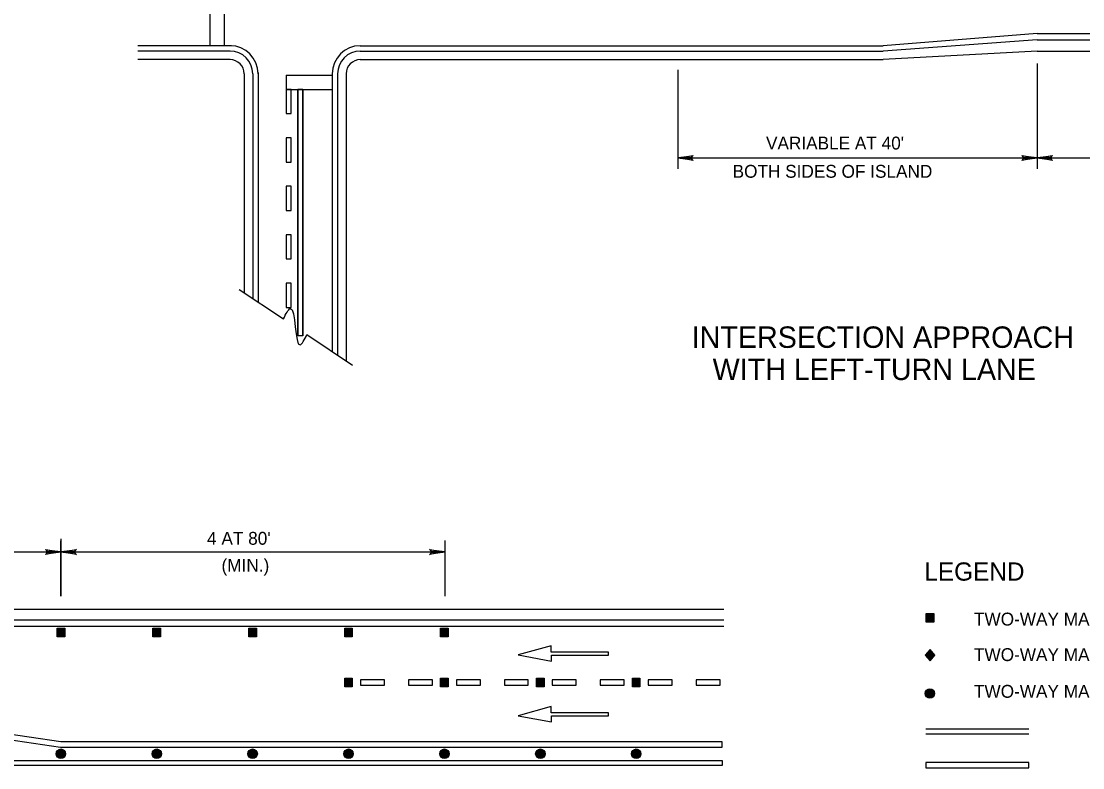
# Model space of a CAD drawing. Extents: x 639362 to 641108, y 298458 to 299646.
# Drawn here: x 639788.7 to 640036.4, y 298754.6 to 298928.7 of the extents above; entities that cross this region are included whole.
import ezdxf

# ---------------------------------------------------------------- set-up
doc = ezdxf.new("R2010")
doc.units = 0
doc.layers.add('2', color=7, linetype='Continuous')
doc.layers.add('3', color=7, linetype='Continuous')

# ---------------------------------------------------------------- blocks, each defined once
blk = doc.blocks.new('RARROW')
at = {"layer": '3'}
blk.add_lwpolyline([(-2.2695, 0.285), (-2.184875, 0.12075), (0, 0), (-2.2695, 0.285), (-2.38575, 0.384625), (0, 0), (-2.183125, -0.108), (-2.262875, -0.2705), (0, 0), (-2.38575, -0.379125), (-2.262875, -0.2705)], dxfattribs=at)

msp = doc.modelspace()

# ---------------------------------------------------------------- linework, layer by layer
at = {"layer": '2'}
for p, q in [((639832.85, 298922.95), (639832.85, 298950.59)), ((639836.15, 298922.95), (639836.15, 298950.59)), ((640025.73, 298925.85), (639989.83, 298922.95)), ((640025.73, 298925.85), (640169.33, 298925.85)), ((639837.77, 298922.95), (639815.93, 298922.95)), ((639867.83, 298922.95), (639989.83, 298922.95)), ((640025.73, 298924.35), (639989.83, 298921.72)), ((640025.73, 298924.35), (640169.33, 298924.35)), ((639837.47, 298921.72), (639815.93, 298921.72)), ((639837.47, 298919.72), (639815.93, 298919.72)), ((639867.83, 298921.72), (639989.83, 298921.72)), ((639867.83, 298919.72), (639989.83, 298919.72)), ((640025.73, 298921.72), (639989.83, 298919.72)), ((640025.73, 298921.72), (640169.33, 298921.72)), ((639941.89, 298917.32), (639941.89, 298894.23)), ((640025.73, 298918.79), (640025.73, 298894.23)), ((639840.75, 298916.44), (639840.75, 298865.35)), ((639842.75, 298916.44), (639842.75, 298864.01)), ((639843.98, 298916.69), (639843.98, 298863.19)), ((639850.53, 298916.09), (639850.53, 298912.79)), ((639850.53, 298916.09), (639861.32, 298916.09)), ((639861.32, 298916.53), (639861.32, 298851.64)), ((639862.55, 298916.44), (639862.55, 298850.81)), ((639864.55, 298916.44), (639864.55, 298849.48)), ((639850.53, 298912.79), (639861.32, 298912.79)), ((639854.47, 298912.79), (639853.27, 298912.79)), ((639853.27, 298912.79), (639853.27, 298855.27)), ((639853.27, 298855.27), (639853.27, 298912.79)), ((639853.27, 298912.79), (639854.47, 298912.79)), ((639854.47, 298855.27), (639854.47, 298912.79)), ((639854.47, 298912.79), (639854.47, 298855.27)), ((639941.89, 298896.78), (640025.73, 298896.78)), ((640025.73, 298896.78), (640169.33, 298896.78)), ((639839.62, 298866.1), (639849.91, 298859.24)), ((639854.47, 298855.27), (639853.27, 298855.27)), ((639855.4, 298855.58), (639866.03, 298848.49)), ((639797.99, 298807.92), (639797.99, 298794.58)), ((639798, 298794.58), (639798, 298807.5)), ((639887.61, 298794.58), (639887.61, 298807.59)), ((639585.52, 298804.88), (639797.99, 298804.88)), ((639798.01, 298804.88), (639887.61, 298804.88)), ((639431.25, 298791.58), (639952.64, 298791.58)), ((639789.19, 298791.58), (639951.12, 298791.58)), ((639431.25, 298789.08), (639952.64, 298789.08)), ((639789.84, 298789.08), (639951.12, 298789.08)), ((639999.84, 298790.57), (640001.61, 298790.57)), ((639999.84, 298788.53), (639999.84, 298790.57)), ((640001.61, 298788.53), (639999.84, 298788.53)), ((640000.01, 298790.4), (640001.43, 298790.4)), ((640000.01, 298788.71), (640000.01, 298790.4)), ((640001.43, 298788.71), (640000.01, 298788.71)), ((640000.19, 298790.22), (640001.26, 298790.22)), ((640000.19, 298788.89), (640000.19, 298790.22)), ((640001.26, 298788.89), (640000.19, 298788.89)), ((640000.37, 298789.07), (640000.37, 298790.04)), ((640000.37, 298790.04), (640001.08, 298790.04)), ((640001.08, 298789.07), (640000.37, 298789.07)), ((640000.55, 298789.87), (640000.9, 298789.87)), ((640000.55, 298789.24), (640000.55, 298789.87)), ((640000.9, 298789.24), (640000.55, 298789.24)), ((640000.72, 298789.69), (640000.72, 298789.42)), ((640000.9, 298789.87), (640000.9, 298789.24)), ((640001.08, 298790.04), (640001.08, 298789.07)), ((640001.26, 298790.22), (640001.26, 298788.89)), ((640001.43, 298790.4), (640001.43, 298788.71)), ((640001.61, 298790.57), (640001.61, 298788.53)), ((639431.25, 298787.58), (639952.64, 298787.58)), ((639790.24, 298787.58), (639951.12, 298787.58)), ((639797.11, 298785.06), (639797.11, 298787.1)), ((639797.11, 298787.1), (639798.88, 298787.1)), ((639797.28, 298785.23), (639797.28, 298786.92)), ((639797.28, 298786.92), (639798.7, 298786.92)), ((639797.46, 298785.41), (639797.46, 298786.74)), ((639797.46, 298786.74), (639798.53, 298786.74)), ((639797.64, 298785.59), (639797.64, 298786.56)), ((639797.64, 298786.56), (639798.35, 298786.56)), ((639797.82, 298785.76), (639797.82, 298786.39)), ((639797.82, 298786.39), (639798.17, 298786.39)), ((639798.17, 298785.76), (639797.82, 298785.76)), ((639798, 298785.94), (639798, 298786.21)), ((639798.17, 298786.39), (639798.17, 298785.76)), ((639798.35, 298786.56), (639798.35, 298785.59)), ((639798.53, 298786.74), (639798.53, 298785.41)), ((639798.7, 298786.92), (639798.7, 298785.23)), ((639798.88, 298787.1), (639798.88, 298785.06)), ((639819.47, 298785.06), (639819.47, 298787.1)), ((639819.47, 298787.1), (639821.25, 298787.1)), ((639819.65, 298785.23), (639819.65, 298786.92)), ((639819.65, 298786.92), (639821.07, 298786.92)), ((639819.83, 298785.41), (639819.83, 298786.74)), ((639819.83, 298786.74), (639820.89, 298786.74)), ((639820.01, 298785.59), (639820.01, 298786.56)), ((639820.01, 298786.56), (639820.72, 298786.56)), ((639820.18, 298785.76), (639820.18, 298786.39)), ((639820.18, 298786.39), (639820.54, 298786.39)), ((639820.54, 298785.76), (639820.18, 298785.76)), ((639820.36, 298785.94), (639820.36, 298786.21)), ((639820.54, 298786.39), (639820.54, 298785.76)), ((639820.72, 298786.56), (639820.72, 298785.59)), ((639820.89, 298786.74), (639820.89, 298785.41)), ((639821.07, 298786.92), (639821.07, 298785.23)), ((639821.25, 298787.1), (639821.25, 298785.06)), ((639841.84, 298785.06), (639841.84, 298787.1)), ((639841.84, 298787.1), (639843.62, 298787.1)), ((639842.02, 298785.23), (639842.02, 298786.92)), ((639842.02, 298786.92), (639843.44, 298786.92)), ((639842.2, 298785.41), (639842.2, 298786.74)), ((639842.2, 298786.74), (639843.26, 298786.74)), ((639842.37, 298785.59), (639842.37, 298786.56)), ((639842.37, 298786.56), (639843.08, 298786.56)), ((639842.55, 298785.76), (639842.55, 298786.39)), ((639842.55, 298786.39), (639842.91, 298786.39)), ((639842.91, 298785.76), (639842.55, 298785.76)), ((639842.73, 298785.94), (639842.73, 298786.21)), ((639842.91, 298786.39), (639842.91, 298785.76)), ((639843.08, 298786.56), (639843.08, 298785.59)), ((639843.26, 298786.74), (639843.26, 298785.41)), ((639843.44, 298786.92), (639843.44, 298785.23)), ((639843.62, 298787.1), (639843.62, 298785.06)), ((639864.21, 298785.06), (639864.21, 298787.1)), ((639864.21, 298787.1), (639865.98, 298787.1)), ((639864.39, 298785.23), (639864.39, 298786.92)), ((639864.39, 298786.92), (639865.81, 298786.92)), ((639864.56, 298785.41), (639864.56, 298786.74)), ((639864.56, 298786.74), (639865.63, 298786.74)), ((639864.74, 298785.59), (639864.74, 298786.56)), ((639864.74, 298786.56), (639865.45, 298786.56)), ((639864.92, 298785.76), (639864.92, 298786.39)), ((639864.92, 298786.39), (639865.27, 298786.39)), ((639865.27, 298785.76), (639864.92, 298785.76)), ((639865.1, 298785.94), (639865.1, 298786.21)), ((639865.27, 298786.39), (639865.27, 298785.76)), ((639865.45, 298786.56), (639865.45, 298785.59)), ((639865.63, 298786.74), (639865.63, 298785.41)), ((639865.81, 298786.92), (639865.81, 298785.23)), ((639865.98, 298787.1), (639865.98, 298785.06)), ((639886.58, 298785.06), (639886.58, 298787.1)), ((639886.58, 298787.1), (639888.35, 298787.1)), ((639886.75, 298785.23), (639886.75, 298786.92)), ((639886.75, 298786.92), (639888.17, 298786.92)), ((639886.93, 298785.41), (639886.93, 298786.74)), ((639886.93, 298786.74), (639888, 298786.74)), ((639887.11, 298785.59), (639887.11, 298786.56)), ((639887.11, 298786.56), (639887.82, 298786.56)), ((639887.29, 298785.76), (639887.29, 298786.39)), ((639887.29, 298786.39), (639887.64, 298786.39)), ((639887.64, 298785.76), (639887.29, 298785.76)), ((639887.47, 298785.94), (639887.47, 298786.21)), ((639887.64, 298786.39), (639887.64, 298785.76)), ((639887.82, 298786.56), (639887.82, 298785.59)), ((639888, 298786.74), (639888, 298785.41)), ((639888.17, 298786.92), (639888.17, 298785.23)), ((639888.35, 298787.1), (639888.35, 298785.06)), ((639798.88, 298785.06), (639797.11, 298785.06)), ((639798.7, 298785.23), (639797.28, 298785.23)), ((639798.53, 298785.41), (639797.46, 298785.41)), ((639798.35, 298785.59), (639797.64, 298785.59)), ((639821.25, 298785.06), (639819.47, 298785.06)), ((639821.07, 298785.23), (639819.65, 298785.23)), ((639820.89, 298785.41), (639819.83, 298785.41)), ((639820.72, 298785.59), (639820.01, 298785.59)), ((639843.62, 298785.06), (639841.84, 298785.06)), ((639843.44, 298785.23), (639842.02, 298785.23)), ((639843.26, 298785.41), (639842.2, 298785.41)), ((639843.08, 298785.59), (639842.37, 298785.59)), ((639865.98, 298785.06), (639864.21, 298785.06)), ((639865.81, 298785.23), (639864.39, 298785.23)), ((639865.63, 298785.41), (639864.56, 298785.41)), ((639865.45, 298785.59), (639864.74, 298785.59)), ((639888.35, 298785.06), (639886.58, 298785.06)), ((639888.17, 298785.23), (639886.75, 298785.23)), ((639888, 298785.41), (639886.93, 298785.41)), ((639887.82, 298785.59), (639887.11, 298785.59)), ((639912.39, 298782.98), (639904.67, 298780.86)), ((639904.67, 298780.86), (639912.47, 298779.39)), ((639912.39, 298781.54), (639912.39, 298782.98)), ((639925.72, 298781.54), (639912.39, 298781.54)), ((639912.47, 298779.39), (639912.47, 298780.83)), ((639912.47, 298780.83), (639925.72, 298780.83)), ((639925.72, 298780.83), (639925.72, 298781.54)), ((640000.75, 298782.1), (639999.62, 298780.8)), ((639999.62, 298780.8), (640000.75, 298779.51)), ((639999.62, 298780.8), (640001.88, 298780.8)), ((639999.73, 298780.92), (640000.85, 298779.63)), ((640000.85, 298781.98), (639999.74, 298780.7)), ((640000.96, 298781.86), (639999.83, 298780.56)), ((639999.83, 298781.04), (640000.96, 298779.75)), ((640001.06, 298781.74), (639999.93, 298780.44)), ((639999.93, 298781.16), (640001.06, 298779.87)), ((640001.17, 298781.62), (640000.04, 298780.32)), ((640000.04, 298781.28), (640001.17, 298779.99)), ((640001.27, 298781.5), (640000.14, 298780.2)), ((640000.14, 298781.4), (640001.27, 298780.11)), ((640000.25, 298781.52), (640001.38, 298780.23)), ((640001.38, 298781.38), (640000.25, 298780.08)), ((640000.35, 298781.64), (640001.48, 298780.35)), ((640001.48, 298781.26), (640000.35, 298779.96)), ((640000.46, 298781.76), (640001.58, 298780.47)), ((640001.58, 298781.14), (640000.46, 298779.84)), ((640000.56, 298781.88), (640001.69, 298780.59)), ((640001.69, 298781.02), (640000.56, 298779.72)), ((640000.67, 298782), (640001.79, 298780.71)), ((640001.79, 298780.9), (640000.67, 298779.6)), ((640001.88, 298780.8), (640000.75, 298782.1)), ((640000.75, 298782.1), (640000.75, 298779.51)), ((640000.75, 298779.51), (640001.88, 298780.8)), ((639864.21, 298773.41), (639864.21, 298775.45)), ((639864.21, 298775.45), (639865.98, 298775.45)), ((639865.98, 298773.41), (639864.21, 298773.41)), ((639864.39, 298773.59), (639864.39, 298775.27)), ((639864.39, 298775.27), (639865.81, 298775.27)), ((639865.81, 298773.59), (639864.39, 298773.59)), ((639864.56, 298773.77), (639864.56, 298775.09)), ((639864.56, 298775.09), (639865.63, 298775.09)), ((639865.63, 298773.77), (639864.56, 298773.77)), ((639864.74, 298773.94), (639864.74, 298774.92)), ((639864.74, 298774.92), (639865.45, 298774.92)), ((639865.45, 298773.94), (639864.74, 298773.94)), ((639864.92, 298774.12), (639864.92, 298774.74)), ((639864.92, 298774.74), (639865.27, 298774.74)), ((639865.27, 298774.12), (639864.92, 298774.12)), ((639865.1, 298774.29), (639865.1, 298774.56)), ((639865.27, 298774.74), (639865.27, 298774.12)), ((639865.45, 298774.92), (639865.45, 298773.94)), ((639865.63, 298775.09), (639865.63, 298773.77)), ((639865.81, 298775.27), (639865.81, 298773.59)), ((639865.98, 298775.45), (639865.98, 298773.41)), ((639873.49, 298775.03), (639867.89, 298775.03)), ((639867.89, 298775.03), (639867.89, 298773.83)), ((639867.89, 298773.83), (639873.49, 298773.83)), ((639873.49, 298773.83), (639873.49, 298775.03)), ((639884.67, 298775.03), (639879.08, 298775.03)), ((639879.08, 298775.03), (639879.08, 298773.83)), ((639879.08, 298773.83), (639884.67, 298773.83)), ((639884.67, 298773.83), (639884.67, 298775.03)), ((639886.58, 298773.41), (639886.58, 298775.45)), ((639886.58, 298775.45), (639888.35, 298775.45)), ((639888.35, 298773.41), (639886.58, 298773.41)), ((639886.75, 298773.59), (639886.75, 298775.27)), ((639886.75, 298775.27), (639888.17, 298775.27)), ((639888.17, 298773.59), (639886.75, 298773.59)), ((639886.93, 298773.77), (639886.93, 298775.09)), ((639886.93, 298775.09), (639888, 298775.09)), ((639888, 298773.77), (639886.93, 298773.77)), ((639887.11, 298773.94), (639887.11, 298774.92)), ((639887.11, 298774.92), (639887.82, 298774.92)), ((639887.82, 298773.94), (639887.11, 298773.94)), ((639887.29, 298774.12), (639887.29, 298774.74)), ((639887.29, 298774.74), (639887.64, 298774.74)), ((639887.64, 298774.12), (639887.29, 298774.12)), ((639887.47, 298774.29), (639887.47, 298774.56)), ((639887.64, 298774.74), (639887.64, 298774.12)), ((639887.82, 298774.92), (639887.82, 298773.94)), ((639888, 298775.09), (639888, 298773.77)), ((639888.17, 298775.27), (639888.17, 298773.59)), ((639888.35, 298775.45), (639888.35, 298773.41)), ((639895.85, 298775.03), (639890.26, 298775.03)), ((639890.26, 298775.03), (639890.26, 298773.83)), ((639890.26, 298773.83), (639895.85, 298773.83)), ((639895.85, 298773.83), (639895.85, 298775.03)), ((639907.04, 298775.03), (639901.45, 298775.03)), ((639901.45, 298775.03), (639901.45, 298773.83)), ((639901.45, 298773.83), (639907.04, 298773.83)), ((639907.04, 298773.83), (639907.04, 298775.03)), ((639908.94, 298773.41), (639908.94, 298775.45)), ((639908.94, 298775.45), (639910.72, 298775.45)), ((639910.72, 298773.41), (639908.94, 298773.41)), ((639909.12, 298773.59), (639909.12, 298775.27)), ((639909.12, 298775.27), (639910.54, 298775.27)), ((639910.54, 298773.59), (639909.12, 298773.59)), ((639909.3, 298773.77), (639909.3, 298775.09)), ((639909.3, 298775.09), (639910.36, 298775.09)), ((639910.36, 298773.77), (639909.3, 298773.77)), ((639909.48, 298773.94), (639909.48, 298774.92)), ((639909.48, 298774.92), (639910.19, 298774.92)), ((639910.19, 298773.94), (639909.48, 298773.94)), ((639909.65, 298774.12), (639909.65, 298774.74)), ((639909.65, 298774.74), (639910.01, 298774.74)), ((639910.01, 298774.12), (639909.65, 298774.12)), ((639909.83, 298774.29), (639909.83, 298774.56)), ((639910.01, 298774.74), (639910.01, 298774.12)), ((639910.19, 298774.92), (639910.19, 298773.94)), ((639910.36, 298775.09), (639910.36, 298773.77)), ((639910.54, 298775.27), (639910.54, 298773.59)), ((639910.72, 298775.45), (639910.72, 298773.41)), ((639918.22, 298775.03), (639912.63, 298775.03)), ((639912.63, 298775.03), (639912.63, 298773.83)), ((639912.63, 298773.83), (639918.22, 298773.83)), ((639918.22, 298773.83), (639918.22, 298775.03)), ((639929.41, 298775.03), (639923.81, 298775.03)), ((639923.81, 298775.03), (639923.81, 298773.83)), ((639923.81, 298773.83), (639929.41, 298773.83)), ((639929.41, 298773.83), (639929.41, 298775.03)), ((639931.31, 298773.41), (639931.31, 298775.45)), ((639931.31, 298775.45), (639933.09, 298775.45)), ((639933.09, 298773.41), (639931.31, 298773.41)), ((639931.49, 298773.59), (639931.49, 298775.27)), ((639931.49, 298775.27), (639932.91, 298775.27)), ((639932.91, 298773.59), (639931.49, 298773.59)), ((639931.67, 298773.77), (639931.67, 298775.09)), ((639931.67, 298775.09), (639932.73, 298775.09)), ((639932.73, 298773.77), (639931.67, 298773.77)), ((639931.84, 298773.94), (639931.84, 298774.92)), ((639931.84, 298774.92), (639932.55, 298774.92)), ((639932.55, 298773.94), (639931.84, 298773.94)), ((639932.02, 298774.12), (639932.02, 298774.74)), ((639932.02, 298774.74), (639932.38, 298774.74)), ((639932.38, 298774.12), (639932.02, 298774.12)), ((639932.2, 298774.29), (639932.2, 298774.56)), ((639932.38, 298774.74), (639932.38, 298774.12)), ((639932.55, 298774.92), (639932.55, 298773.94)), ((639932.73, 298775.09), (639932.73, 298773.77)), ((639932.91, 298775.27), (639932.91, 298773.59)), ((639933.09, 298775.45), (639933.09, 298773.41)), ((639940.59, 298775.03), (639935, 298775.03)), ((639935, 298775.03), (639935, 298773.83)), ((639935, 298773.83), (639940.59, 298773.83)), ((639940.59, 298773.83), (639940.59, 298775.03)), ((639951.77, 298775.03), (639946.18, 298775.03)), ((639946.18, 298775.03), (639946.18, 298773.83)), ((639946.18, 298773.83), (639951.77, 298773.83)), ((639951.77, 298773.83), (639951.77, 298775.03)), ((639719.64, 298770.96), (639797.91, 298759.39)), ((639798, 298760.59), (639719.73, 298772.16)), ((639912.39, 298768.82), (639904.67, 298766.7)), ((639912.39, 298767.38), (639912.39, 298768.82)), ((639904.67, 298766.7), (639912.47, 298765.23)), ((639925.72, 298767.38), (639912.39, 298767.38)), ((639912.47, 298765.23), (639912.47, 298766.67)), ((639912.47, 298766.67), (639925.72, 298766.67)), ((639925.72, 298766.67), (639925.72, 298767.38)), ((640023.81, 298763.56), (639999.76, 298763.56)), ((640023.81, 298762.36), (639999.76, 298762.36)), ((639797.91, 298759.39), (639952.26, 298759.39)), ((639952.26, 298760.59), (639798, 298760.59)), ((639952.26, 298759.39), (639952.26, 298760.59)), ((639663.88, 298756.28), (639952.26, 298756.28)), ((639952.26, 298756.28), (639952.26, 298755.08)), ((639952.26, 298755.08), (639663.79, 298755.08)), ((640023.81, 298755.75), (639999.76, 298755.75)), ((639999.76, 298755.75), (639999.76, 298754.55)), ((639999.76, 298754.55), (640023.81, 298754.55)), ((640023.81, 298754.55), (640023.81, 298755.75))]:
    msp.add_line(p, q, dxfattribs=at)
for points in [[(639850.53, 298907.13), (639851.73, 298907.13), (639851.73, 298912.79), (639850.53, 298912.79)], [(639850.53, 298895.83), (639851.73, 298895.83), (639851.73, 298901.48), (639850.53, 298901.48)], [(639850.53, 298884.52), (639851.73, 298884.52), (639851.73, 298890.18), (639850.53, 298890.18)], [(639850.53, 298873.22), (639851.73, 298873.22), (639851.73, 298878.87), (639850.53, 298878.87)], [(639850.53, 298861.91), (639851.73, 298861.91), (639851.73, 298867.57), (639850.53, 298867.57)]]:
    msp.add_lwpolyline(points, close=True, dxfattribs=at)
for centre, radius in [((640000.72, 298771.89), 1.1), ((640000.72, 298771.89), 1.02), ((640000.72, 298771.89), 0.946), ((640000.72, 298771.89), 0.868), ((640000.72, 298771.89), 0.789), ((640000.72, 298771.89), 0.711), ((640000.72, 298771.89), 0.633), ((640000.72, 298771.89), 0.554), ((640000.72, 298771.89), 0.476), ((640000.72, 298771.89), 0.398), ((640000.72, 298771.89), 0.32), ((640000.72, 298771.89), 0.241), ((640000.72, 298771.89), 0.163), ((640000.72, 298771.89), 0.0846), ((639798.01, 298757.83), 1.1), ((639798.01, 298757.83), 1.02), ((639798.01, 298757.83), 0.946), ((639798.01, 298757.83), 0.868), ((639798.01, 298757.83), 0.789), ((639798.01, 298757.83), 0.711), ((639798.01, 298757.83), 0.633), ((639820.36, 298757.83), 1.1), ((639820.36, 298757.83), 1.02), ((639820.36, 298757.83), 0.946), ((639820.36, 298757.83), 0.868), ((639820.36, 298757.83), 0.789), ((639820.36, 298757.83), 0.711), ((639820.36, 298757.83), 0.633), ((639842.73, 298757.83), 1.1), ((639842.73, 298757.83), 1.02), ((639842.73, 298757.83), 0.946), ((639842.73, 298757.83), 0.868), ((639842.73, 298757.83), 0.789), ((639842.73, 298757.83), 0.711), ((639842.73, 298757.83), 0.633), ((639865.1, 298757.83), 1.1), ((639865.1, 298757.83), 1.02), ((639865.1, 298757.83), 0.946), ((639865.1, 298757.83), 0.868), ((639865.1, 298757.83), 0.789), ((639865.1, 298757.83), 0.711), ((639865.1, 298757.83), 0.633), ((639887.47, 298757.83), 1.1), ((639887.47, 298757.83), 1.02), ((639887.47, 298757.83), 0.946), ((639887.47, 298757.83), 0.868), ((639887.47, 298757.83), 0.789), ((639887.47, 298757.83), 0.711), ((639887.47, 298757.83), 0.633), ((639909.85, 298757.83), 1.1), ((639909.85, 298757.83), 1.02), ((639909.85, 298757.83), 0.946), ((639909.85, 298757.83), 0.868), ((639909.85, 298757.83), 0.789), ((639909.85, 298757.83), 0.711), ((639909.85, 298757.83), 0.633), ((639932.22, 298757.83), 1.1), ((639932.22, 298757.83), 1.02), ((639932.22, 298757.83), 0.946), ((639932.22, 298757.83), 0.868), ((639932.22, 298757.83), 0.789), ((639932.22, 298757.83), 0.711), ((639932.22, 298757.83), 0.633), ((639798.01, 298757.83), 0.554), ((639798.01, 298757.83), 0.476), ((639798.01, 298757.83), 0.398), ((639798.01, 298757.83), 0.32), ((639798.01, 298757.83), 0.241), ((639798.01, 298757.83), 0.163), ((639798.01, 298757.83), 0.0846), ((639820.36, 298757.83), 0.554), ((639820.36, 298757.83), 0.476), ((639820.36, 298757.83), 0.398), ((639820.36, 298757.83), 0.32), ((639820.36, 298757.83), 0.241), ((639820.36, 298757.83), 0.163), ((639820.36, 298757.83), 0.0846), ((639842.73, 298757.83), 0.554), ((639842.73, 298757.83), 0.476), ((639842.73, 298757.83), 0.398), ((639842.73, 298757.83), 0.32), ((639842.73, 298757.83), 0.241), ((639842.73, 298757.83), 0.163), ((639842.73, 298757.83), 0.0846), ((639865.1, 298757.83), 0.554), ((639865.1, 298757.83), 0.476), ((639865.1, 298757.83), 0.398), ((639865.1, 298757.83), 0.32), ((639865.1, 298757.83), 0.241), ((639865.1, 298757.83), 0.163), ((639865.1, 298757.83), 0.0846), ((639887.47, 298757.83), 0.554), ((639887.47, 298757.83), 0.476), ((639887.47, 298757.83), 0.398), ((639887.47, 298757.83), 0.32), ((639887.47, 298757.83), 0.241), ((639887.47, 298757.83), 0.163), ((639887.47, 298757.83), 0.0846), ((639909.85, 298757.83), 0.554), ((639909.85, 298757.83), 0.476), ((639909.85, 298757.83), 0.398), ((639909.85, 298757.83), 0.32), ((639909.85, 298757.83), 0.241), ((639909.85, 298757.83), 0.163), ((639909.85, 298757.83), 0.0846), ((639932.22, 298757.83), 0.554), ((639932.22, 298757.83), 0.476), ((639932.22, 298757.83), 0.398), ((639932.22, 298757.83), 0.32), ((639932.22, 298757.83), 0.241), ((639932.22, 298757.83), 0.163), ((639932.22, 298757.83), 0.0846)]:
    msp.add_circle(centre, radius, dxfattribs=at)
for centre, radius, start, end in [((639837.47, 298916.44), 6.52, 0, 90), ((639867.83, 298916.44), 6.52, 90, 180), ((639837.47, 298916.44), 5.28, 0, 90), ((639837.47, 298916.44), 3.28, 0, 90), ((639867.83, 298916.44), 5.28, 90, 180), ((639867.83, 298916.44), 3.28, 90, 180)]:
    msp.add_arc(centre, radius, start, end, dxfattribs=at)
msp.add_spline([(639849.91, 298859.24), (639851.51, 298861.66), (639853.8, 298853.18), (639855.4, 298855.58)], degree=3, dxfattribs=at)

# ---------------------------------------------------------------- block references
at = {"layer": '2', "xscale": 1.5089217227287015, "yscale": 1.5711553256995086, "rotation": 180}
for p in [(639941.89, 298896.78), (640025.73, 298896.78), (639798.01, 298804.88)]:
    msp.add_blockref('RARROW', p, dxfattribs=at)
at = {"layer": '2', "xscale": 1.5089217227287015, "yscale": 1.5711553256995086}
for p in [(640025.73, 298896.78), (639797.99, 298804.88), (639887.61, 298804.88)]:
    msp.add_blockref('RARROW', p, dxfattribs=at)

# ---------------------------------------------------------------- texts
at = {"layer": '2'}
for s, height, p in [("VARIABLE AT 40'", 3, (639962.49, 298898.76)), ('BOTH SIDES OF ISLAND', 3, (639954.7, 298892.17)), ('INTERSECTION APPROACH', 5, (639945.16, 298852.49)), ('WITH LEFT-TURN LANE', 5, (639950.04, 298844.99)), ("4 AT 80'", 3, (639832.1, 298806.57)), ('(MIN.)', 3, (639835.47, 298800.27)), ('LEGEND', 4.25, (639999.42, 298798.2)), ('TWO-WAY MARKER WITH WHITE/BLANK REFLECTOR', 3, (640011, 298787.73)), ('TWO-WAY MARKER WITH YELLOW/YELLOW REFLECTOR', 3, (640011, 298770.88))]:
    msp.add_text(s, height=height, dxfattribs=at).set_placement(p)
msp.add_text('TWO-WAY MARKER WITH YELLOW/BLANK REFLECTOR', height=3, rotation=360, dxfattribs=at).set_placement((640011, 298779.44))

doc.saveas('drawing.dxf')
